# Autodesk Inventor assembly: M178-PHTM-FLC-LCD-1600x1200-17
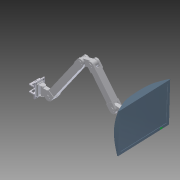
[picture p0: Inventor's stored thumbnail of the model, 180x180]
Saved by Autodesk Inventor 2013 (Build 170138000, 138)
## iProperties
Created: 2004-11
Part Number: M178-PHTM-FLC-LCD-1600x1200-17
Document SubType Name: Assembly
Designer: Autodesk, Inc.
Manufacturer: Standard
Standards Organization: Custom
Mass: 6597.32 g
Surface Area: 5882.8 cm^2
Volume: 6416.93 cm^3
Density: 1.02811 g/cm^3
CAGE: 1LJX3
Dept. ID: Product Design
Description #2: ---
Finish #1: ---
Finish #2: ---
Material ID: ---
Project Number: ---
Author: Autodesk, Inc.
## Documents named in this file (11)
- Z:\_DATEN\Test Station\Components\Monitor Phantom.iam
- Z:\_DATEN\Test Station\Components\FLC-LCD-1600x1200-17.ipt
- Z:\_DATEN\Test Station\Components\SwingArm.iam
- Z:\_DATEN\Test Station\Components\Monitor Arm Ref Cross Bar.ipt
- Z:\_DATEN\Test Station\Components\M178-3502.ipt
- Z:\_DATEN\Test Station\Components\24-112-8.ipt
- Z:\_DATEN\Test Station\Components\20-058.ipt
- Z:\_DATEN\Test Station\Components\24-18-5.ipt
- C:\Users\kelleyb.ADS\Desktop\Samples MIGRATED 2009 224 RTM_1\Standard Parts\Test Station Content\Extrusions\40 Series Profiles.ipt
- C:\Users\kelleyb.ADS\Desktop\Samples MIGRATED 2009 224 RTM_1\Standard Parts\Test Station Content\Fastners\2X-YYY-ZZ IPS Screws.ipt
- C:\Users\kelleyb.ADS\Desktop\Samples MIGRATED 2009 224 RTM_1\Standard Parts\Test Station Content\Fastners\20-XXX TSlot Nuts.ipt
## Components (17 placed, 7 different names)
1. FLC-LCD-1600x1200-17:1
2. SwingArm:1 [sub-assembly] — Mate:1, Flush:1, Mate:2, Mate:4, Insert:3, Insert:4, Mate:12, Insert:9, Insert:10
3. Monitor Arm Ref Cross Bar:1 — Mate:1, Mate:3, Mate:11
4. M178-3502:1 — Flush:2, Mate:3, Mate:4, Insert:5, Insert:6, Mate:7, Angle:1, Angle:2
5. 24-112-8:1 — Insert:6, Mate:5
6. 24-112-8:2 — Insert:5, Mate:6
7. 24-18-5:5 — Insert:4
8. 24-18-5:6 — Insert:3
9. 20-058:1 — Mate:5, Mate:7, Flush:3, Angle:1
10. 20-058:2 — Mate:6, Flush:3, Angle:2
11. M178-3502:2 — Flush:4, Insert:7, Insert:8, Angle:3, Angle:4, Mate:8, Mate:11, Mate:12
12. 24-112-8:3 — Insert:7, Mate:10
13. 24-112-8:4 — Insert:8, Mate:9
14. 24-18-5:7 — Insert:10
15. 24-18-5:8 — Insert:9
16. 20-058:3 — Angle:4, Flush:5, Mate:8, Mate:10
17. 20-058:4 — Angle:3, Flush:5, Mate:9
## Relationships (29: Mate 12, Insert 8, Flush 5, Angle 4)
- Mate:1: SwingArm:1 ↔ Monitor Arm Ref Cross Bar:1
- Flush:1: SwingArm:1
- Mate:2: SwingArm:1
- Flush:2: M178-3502:1
- Mate:3: Monitor Arm Ref Cross Bar:1 ↔ M178-3502:1
- Mate:4: SwingArm:1 ↔ M178-3502:1
- Insert:3: SwingArm:1 ↔ 24-18-5:6
- Insert:4: SwingArm:1 ↔ 24-18-5:5
- Insert:5: M178-3502:1 ↔ 24-112-8:2
- Insert:6: M178-3502:1 ↔ 24-112-8:1
- Mate:5: 24-112-8:1 ↔ 20-058:1
- Mate:6: 24-112-8:2 ↔ 20-058:2
- Mate:7: M178-3502:1 ↔ 20-058:1
- Flush:3: 20-058:1 ↔ 20-058:2
- Angle:1: M178-3502:1 ↔ 20-058:1
- Angle:2: M178-3502:1 ↔ 20-058:2
- Flush:4: M178-3502:2
- Insert:7: M178-3502:2 ↔ 24-112-8:3
- Insert:8: M178-3502:2 ↔ 24-112-8:4
- Angle:3: M178-3502:2 ↔ 20-058:4
- Angle:4: M178-3502:2 ↔ 20-058:3
- Flush:5: 20-058:3 ↔ 20-058:4
- Mate:8: M178-3502:2 ↔ 20-058:3
- Mate:9: 24-112-8:4 ↔ 20-058:4
- Mate:10: 24-112-8:3 ↔ 20-058:3
- Mate:11: Monitor Arm Ref Cross Bar:1 ↔ M178-3502:2
- Mate:12: SwingArm:1 ↔ M178-3502:2
- Insert:9: SwingArm:1 ↔ 24-18-5:8
- Insert:10: SwingArm:1 ↔ 24-18-5:7
